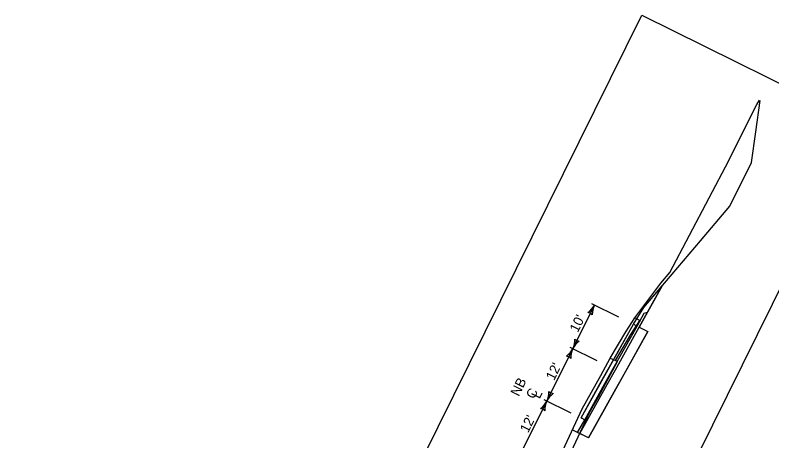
# Model space of a CAD drawing. Extents: x 14104283 to 14121738, y 8635219 to 8671666.
# Drawn here: x 14117091 to 14117712, y 8667464 to 8667813 of the extents above; entities that cross this region are included whole.
import ezdxf

# ---------------------------------------------------------------- set-up
doc = ezdxf.new("R2010")
doc.units = 0
for name, color, linetype in [('Default', 7, 'Continuous'), ('dsnCellElements', 7, 'Continuous'), ('dsnShadingPaved', 7, 'Continuous'), ('dsnTextFinalPlan', 7, 'Continuous'), ('TC_Subbase', 7, 'Continuous'), ('TC_SubgradeTreatment', 7, 'Continuous'), ('TC_SubstrataExistingPavement', 7, 'Continuous'), ('Terrain', 7, 'Continuous')]:
    doc.layers.add(name, color=color, linetype=linetype)

# ---------------------------------------------------------------- blocks, each defined once
blk = doc.blocks.new('LT')
at = {"layer": 'dsnCellElements'}
for centre, radius, start, end in [((-3.56, 0), 1.64, 342.2666, 17.7333), ((0, 4.25), 4.25, 241.9275, 270), ((0, -4.25), 4.25, 90, 118.0725)]:
    blk.add_arc(centre, radius, start, end, dxfattribs=at)

msp = doc.modelspace()

# ---------------------------------------------------------------- linework, layer by layer
at = {"layer": 'Default'}
for p, q in [((14117598.68, 8667559.44), (14117601.66, 8667557.97)), ((14117555.7, 8667482.41), (14117558.69, 8667480.93))]:
    msp.add_line(p, q, dxfattribs=at)
for points in [[(14117555.7, 8667482.41), (14117572.34, 8667512.24), (14117579.14, 8667524.42), (14117598.68, 8667559.44)], [(14117558.69, 8667480.93), (14117575.33, 8667510.77), (14117582.13, 8667522.95), (14117601.66, 8667557.97)]]:
    msp.add_lwpolyline(points, dxfattribs=at)
at = {"layer": 'dsnShadingPaved'}
msp.add_lwpolyline([(14117555.7, 8667482.41), (14117598.68, 8667559.44), (14117607.21, 8667573.1), (14117622.34, 8667590.93), (14117603.46, 8667557.08), (14117610.61, 8667553.5), (14117561.78, 8667465.97), (14117552.83, 8667470.43), (14117558.69, 8667480.93)], close=True, dxfattribs=at)
at = {"layer": 'dsnTextFinalPlan'}
for p, q in [((14117548.9, 8667539.32), (14117566.63, 8667575.17)), ((14117564.18, 8667576.38), (14117586.41, 8667565.39)), ((14117527.63, 8667496.29), (14117548.9, 8667539.32)), ((14117546.45, 8667540.53), (14117568.68, 8667529.54)), ((14117506.35, 8667453.26), (14117527.63, 8667496.29)), ((14117525.18, 8667497.5), (14117547.41, 8667486.51))]:
    msp.add_line(p, q, dxfattribs=at)
msp.add_lwpolyline([(14117090.92, 8666772.68), (14117605.48, 8667813.41), (14117786.12, 8667724.1), (14117271.55, 8666683.37)], close=True, dxfattribs=at)
at = {"layer": 'TC_Subbase'}
for p, q in [((14117610.24, 8667569.24), (14117622.34, 8667590.93)), ((14117601.66, 8667557.97), (14117607.52, 8667568.47)), ((14117607.52, 8667568.47), (14117610.24, 8667569.24)), ((14117552.83, 8667470.43), (14117558.69, 8667480.93)), ((14117548.56, 8667472.55), (14117554.63, 8667469.55))]:
    msp.add_line(p, q, dxfattribs=at)
msp.add_lwpolyline([(14117554.63, 8667469.55), (14117577.13, 8667509.88), (14117583.92, 8667522.06), (14117610.24, 8667569.24)], dxfattribs=at)
at = {"layer": 'TC_SubgradeTreatment'}
for p, q in [((14117603.46, 8667557.08), (14117610.61, 8667553.5)), ((14117561.78, 8667465.97), (14117554.63, 8667469.55))]:
    msp.add_line(p, q, dxfattribs=at)
msp.add_lwpolyline([(14117561.78, 8667465.97), (14117584.28, 8667506.3), (14117591.07, 8667518.48), (14117610.61, 8667553.5)], dxfattribs=at)
at = {"layer": 'TC_SubstrataExistingPavement'}
for points in [[(14117579.66, 8667531.63), (14117583.85, 8667529.56), (14117596.54, 8667551), (14117604.08, 8667562.62), (14117599.9, 8667564.69)], [(14117538.36, 8667450.82), (14117544.34, 8667447.86), (14117549.44, 8667458.73), (14117562.63, 8667486.83), (14117570.07, 8667499.82), (14117585.64, 8667528.68), (14117583.85, 8667529.56)]]:
    msp.add_lwpolyline(points, dxfattribs=at)
at = {"layer": 'Terrain'}
for points in [[(14117598.68, 8667559.44), (14117607.21, 8667573.1), (14117653.67, 8667627.85), (14117677.86, 8667656.36), (14117695.64, 8667692.3), (14117699.13, 8667717.39), (14117702.74, 8667743.39)], [(14117677.14, 8667693.9), (14117679.3, 8667698.54), (14117699.97, 8667739.99), (14117702.29, 8667743.61)], [(14117532.86, 8667440.08), (14117535.95, 8667445.67), (14117538.96, 8667452.1), (14117556.65, 8667489.78), (14117571.88, 8667517.2), (14117579.66, 8667531.63), (14117592.36, 8667553.06), (14117599.9, 8667564.69), (14117621.16, 8667593.21), (14117628.6, 8667602.05), (14117677.14, 8667693.9)]]:
    msp.add_lwpolyline(points, dxfattribs=at)

# ---------------------------------------------------------------- block references
at = {"layer": 'dsnTextFinalPlan'}
for p, xscale, yscale, rotation in [((14117566.63, 8667575.17), 3.942400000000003, 3.9424000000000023, 63.69110745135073), ((14117548.9, 8667539.32), 3.942400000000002, 3.9424000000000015, -116.30889254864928), ((14117548.9, 8667539.32), 3.942400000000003, 3.9424000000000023, 63.69110745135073), ((14117527.63, 8667496.29), 3.942400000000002, 3.9424000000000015, -116.30889254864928), ((14117527.63, 8667496.29), 3.942400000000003, 3.9424000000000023, 63.69110745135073)]:
    msp.add_blockref('LT', p, dxfattribs=dict(at, xscale=xscale, yscale=yscale, rotation=rotation))

# ---------------------------------------------------------------- texts
for s, p in [("10'", (14117553.01, 8667552.1)), ("12'", (14117533.51, 8667512.65)), ('NB', (14117504.56, 8667499.61)), ('C', (14117517.19, 8667497.41)), ('L', (14117521.63, 8667497.65)), ("12'", (14117512.23, 8667469.63))]:
    msp.add_text(s, height=8, rotation=63.69111, dxfattribs=at).set_placement(p)

doc.saveas('drawing.dxf')
